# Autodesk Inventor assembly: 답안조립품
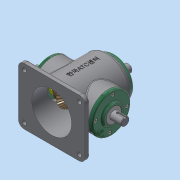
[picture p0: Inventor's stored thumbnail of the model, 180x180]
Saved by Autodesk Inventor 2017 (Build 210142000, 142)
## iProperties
Part Number: 답안조립품
Material: 일반
Document SubType Name: Assembly
Designer: MRC
Author: MRC
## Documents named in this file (16)
- C:\Users\MRC\Desktop\710116V1007\답안조립품.iam
- C:\Users\MRC\Desktop\710116V1007\본체.ipt
- C:\Users\MRC\Desktop\710116V1007\메인 베벨기어.ipt
- C:\Users\MRC\Desktop\710116V1007\메인 축.ipt
- 메인 축.ipt
- C:\Users\MRC\Desktop\710116V1007\베어링 6203.ipt
- C:\Users\MRC\Desktop\710116V1007\볼트 M4.ipt
- 볼트 M4.ipt
- C:\Users\MRC\Desktop\710116V1007\서브 베벨기어.ipt
- C:\Users\MRC\Desktop\710116V1007\서브 축.ipt
- 서브 축.ipt
- C:\Users\MRC\Desktop\710116V1007\오일 실.ipt
- 오일 실.ipt
- C:\Users\MRC\Desktop\710116V1007\커버.ipt
- C:\Users\MRC\Desktop\710116V1007\키 4x4.ipt
- C:\Users\MRC\Desktop\710116V1007\키 5x5.ipt
